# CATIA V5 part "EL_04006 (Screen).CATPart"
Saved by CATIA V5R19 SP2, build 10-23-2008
Part number: Part940
Bounding box of the stored display mesh (mm): x 0 to 120, y 0 to 74, z -6 to 4.7
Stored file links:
  C:\Users\thoma\Desktop\EPSA\ELIZ-2021\EL_Electrical\CATIA\EL_A0100 (Dash Panel)\EL_04006 (Screen).CATPart
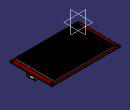
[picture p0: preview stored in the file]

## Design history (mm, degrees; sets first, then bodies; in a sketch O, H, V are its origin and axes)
Body1 (main body)
  Sketch1 on xy-plane, origin (0, 0, 0), H (1, 0, 0), V (0, 1, 0)
    line L1 (0, 0) -> (120, 0)
    line L2 (120, 0) -> (120, 74)
    line L3 (120, 74) -> (0, 74)
    line L4 (0, 74) -> (0, 0)
    circle A1 centre (3.2, 70.8) radius 1.6
    point P4 (3.2, 70.8)
    circle A2 centre (116.8, 70.8) radius 1.6
    point P5 (116.8, 70.8)
    circle A3 centre (116.8, 3.2) radius 1.6
    point P6 (116.8, 3.2)
    circle A4 centre (3.2, 3.2) radius 1.6
    point P7 (3.2, 3.2)
    construction line L5 (3.2, 70.8) -> (116.8, 70.8)
    axis line L6 (3.2, 3.2) -> (116.8, 3.2)
    length L3 = 120
    length L2 = 74
    radius A1 = 1.6
    radius A4 = 1.6
    radius A2 = 1.6
    radius A3 = 1.6
    distance L3 P4 = 3.2
    distance P4 P5 = 113.6
    distance P7 P6 = 113.6
    distance P4 L4 = 3.2
    distance P7 L4 = 3.2
    distance L5 L6 = 67.6
    horizontal: L1 H, L3 H, L5 H, L6 H
    vertical: L2 V, L4 V
  Pad1: profile Sketch1, direction (0, 0, 1), length 1.6
  Sketch2 on end face of Pad1, origin (0, 0, 1.6), H (1, 0, 0), V (0, 1, 0)
    line L1 (7.25, 70.8) -> (112.75, 70.8)
    line L2 (112.75, 70.8) -> (112.75, 3.2)
    line L3 (112.75, 3.2) -> (7.25, 3.2)
    line L4 (7.25, 3.2) -> (7.25, 70.8)
    reference projected line E1 (120, 74) -> (0, 74) from edge [face of Pad1 from Sketch1.L3 | end face of Pad1]
    reference projected line E2 (120, 0) -> (120, 74) from edge [face of Pad1 from Sketch1.L2 | end face of Pad1]
    length L1 = 105.5
    length L2 = 67.6
    distance L1 E1 = 3.2
    distance E2 L2 = 7.25
    horizontal: L1 H, L3 H
    vertical: L2 V, L4 V
  Pad2: profile Sketch2, direction (0, 0, 1), length 3.1
  Sketch3 on start face of Pad1, origin (0, 0, 0), H (1, 0, 0), V (0, -1, 0)
    point P1 (9.85, 0)
    line L1 (9.85, 0) -> (23.85, 0)
    line L2 (23.85, 0) -> (23.85, -13.1)
    line L3 (23.85, -13.1) -> (9.85, -13.1)
    line L4 (9.85, -13.1) -> (9.85, 0)
    reference projected line E1 (0, -74) -> (0, 0) from edge [start face of Pad1 | face of Pad1 from Sketch1.L4]
    length L2 = 13.1
    length L3 = 14
    distance L4 E1 = 9.85
    coincidence: P1 H
    horizontal: L1 H, L3 H
    vertical: L2 V, L4 V
  Pad3: profile Sketch3, direction (0, 0, -1), length 2.7
  Sketch4 on start face of Pad1, origin (0, 0, 0), H (1, 0, 0), V (0, -1, 0)
    line L1 (112.2, -29.4) -> (120, -29.4)
    line L2 (120, -29.4) -> (120, -44.52)
    line L3 (120, -44.52) -> (112.2, -44.52)
    line L4 (112.2, -44.52) -> (112.2, -29.4)
    reference projected line E1 (120, 0) -> (120, -74) from edge [start face of Pad1 | face of Pad1 from Sketch1.L2]
    reference projected line E2 (0, 0) -> (120, 0) from edge [start face of Pad1 | face of Pad3]
    length L1 = 7.8
    length L4 = 15.12
    distance L1 E2 = 29.4
    horizontal: L1 H, L3 H
    vertical: L2 V, L4 V
    coincidence: L2 E1
  Pad4: profile Sketch4, direction (0, 0, -1), length 6
  Sketch5 on face of Pad4, origin (120, 0, 0), H (0, 1, 0), V (0, 0, 1)
    line L1 (29.9, -1) -> (44.02, -1)
    line L2 (44.02, -1) -> (44.02, -5)
    line L3 (29.9, -5) -> (29.9, -1)
    reference projected line E1 (29.4, 0) -> (29.4, -6) from edge [face of Pad4 from Sketch4.L1 | face of Pad4]
    reference projected line E2 (44.52, 0) -> (44.52, -6) from edge [face of Pad4 | face of Pad4 from Sketch4.L3]
    line L4 (29.9, -5) -> (31.9, -5)
    line L5 (31.9, -5) -> (31.9, -7.3581)
    line L6 (31.9, -7.3581) -> (33.4, -7.3581)
    line L7 (33.4, -7.3581) -> (33.4, -5)
    point P8 (33.4, -5)
    line L8 (33.4, -5) -> (40.52, -5)
    line L9 (40.52, -5) -> (40.52, -7.3581)
    point P10 (40.52, -7.3581)
    line L10 (40.52, -7.3581) -> (42.02, -7.3581)
    line L11 (42.02, -7.3581) -> (42.02, -5)
    point P12 (42.02, -5)
    line L12 (42.02, -5) -> (44.02, -5)
    reference projected line E3 (44.52, -6) -> (29.4, -6) from edge [face of Pad4 from Sketch4.L2 | end face of Pad4]
    reference projected line E4 (0, 0) -> (74, 0) from edge [start face of Pad1 | face of Pad4]
    point P13 (28.9, 0)
    line L13 (28.9, 0) -> (45.02, 0)
    line L14 (45.02, 0) -> (45.02, -0.2)
    line L15 (45.02, -0.2) -> (28.9, -0.2)
    line L16 (28.9, -0.2) -> (28.9, 0)
    point P16 (28.9, -0.2)
    distance L3 E1 = 0.5
    distance L2 E2 = 0.5
    length L4 = 2
    length L12 = 2
    length L6 = 1.5
    length L10 = 1.5
    length L7 = 2.3581
    distance L8 E3 = 1
    distance L1 E4 = 1
    length L14 = 0.2
    distance L3 P16 = 1
    distance L14 L2 = 1
    horizontal: L1 H, L4 H, L6 H, L8 H, L10 H, L12 H, L13 H, L15 H
    vertical: L2 V, L3 V, L5 V, L7 V, L9 V, L11 V, L14 V, L16 V
    coincidence: P8 L4, P10 L6, P12 L4, P13 H
  Pocket1: profile Sketch5, direction (-1, 0, 0), length 6
  Sketch6 on face of Pad3, origin (0, 0, 0), H (1, 0, 0), V (0, 0, 1)
    line L1 (11.85, -1.5) -> (23.35, -1.5)
    line L2 (23.35, -1.5) -> (23.35, -2.5)
    line L3 (23.35, -2.5) -> (11.85, -2.5)
    line L4 (11.85, -2.5) -> (11.85, -1.5)
    reference projected line E1 (9.85, 0) -> (9.85, -2.7) from edge [face of Pad3 from Sketch3.L4 | face of Pad3]
    reference projected line E2 (23.85, 0) -> (23.85, -2.7) from edge [face of Pad3 | face of Pad3 from Sketch3.L2]
    reference projected line E3 (23.85, -2.7) -> (9.85, -2.7) from edge [face of Pad3 from Sketch3.L1 | end face of Pad3]
    distance L4 E1 = 2
    distance E2 L2 = 0.5
    length L4 = 1
    distance L3 E3 = 0.2
    horizontal: L1 H, L3 H
    vertical: L2 V, L4 V
  Pocket2: profile Sketch6, direction (0, 1, 0), length 12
